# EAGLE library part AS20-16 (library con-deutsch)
DEUTSCH Connector
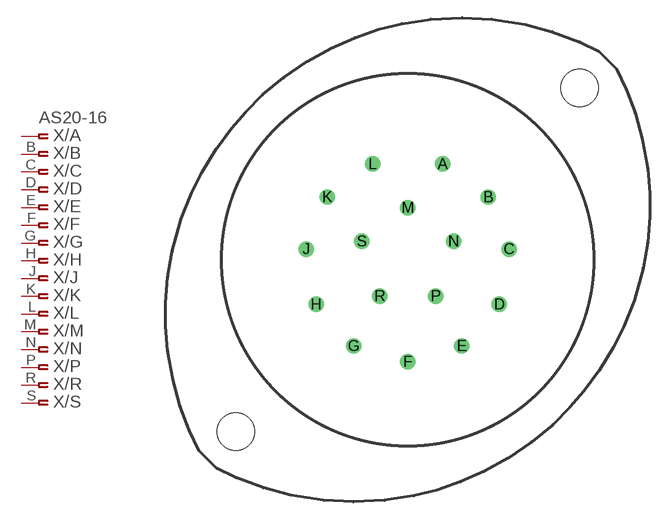
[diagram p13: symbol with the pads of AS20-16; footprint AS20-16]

Designator prefix X; gates /A=PINF_VAL /B=ASPINF /C=ASPINF /D=ASPINF /E=ASPINF /F=ASPINF /G=ASPINF /H=ASPINF /J=ASPINF /K=ASPINF /L=ASPINF /M=ASPINF /N=ASPINF /P=ASPINF /R=ASPINF /S=ASPINF

## AS20-16 (OC_FARNELL: unknown; OC_NEWARK: unknown)  [AS20-16]
A  /A:1  pas
B  /B:1  pas
C  /C:1  pas
D  /D:1  pas
E  /E:1  pas
F  /F:1  pas
G  /G:1  pas
H  /H:1  pas
J  /J:1  pas
K  /K:1  pas
L  /L:1  pas
M  /M:1  pas
N  /N:1  pas
P  /P:1  pas
R  /R:1  pas
S  /S:1  pas

## Footprint AS20-16 (pad centres in mm)
DEUTSCH Connector
drill 0.813 round: A 2.997,8.179; B 6.883,5.359; C 8.661,0.914; D 7.823,-3.81; E 4.623,-7.366; F 0,-8.712; G -4.623,-7.366; H -7.823,-3.81; J -8.661,0.914; K -6.883,5.359; L -2.997,8.179; M 0,4.445; N 3.912,1.575; P 2.388,-3.099; R -2.388,-3.099; S -3.912,1.575
hole 3.2 at -14.7,-14.7
hole 3.2 at 14.7,14.7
